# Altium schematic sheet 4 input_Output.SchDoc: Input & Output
size A4
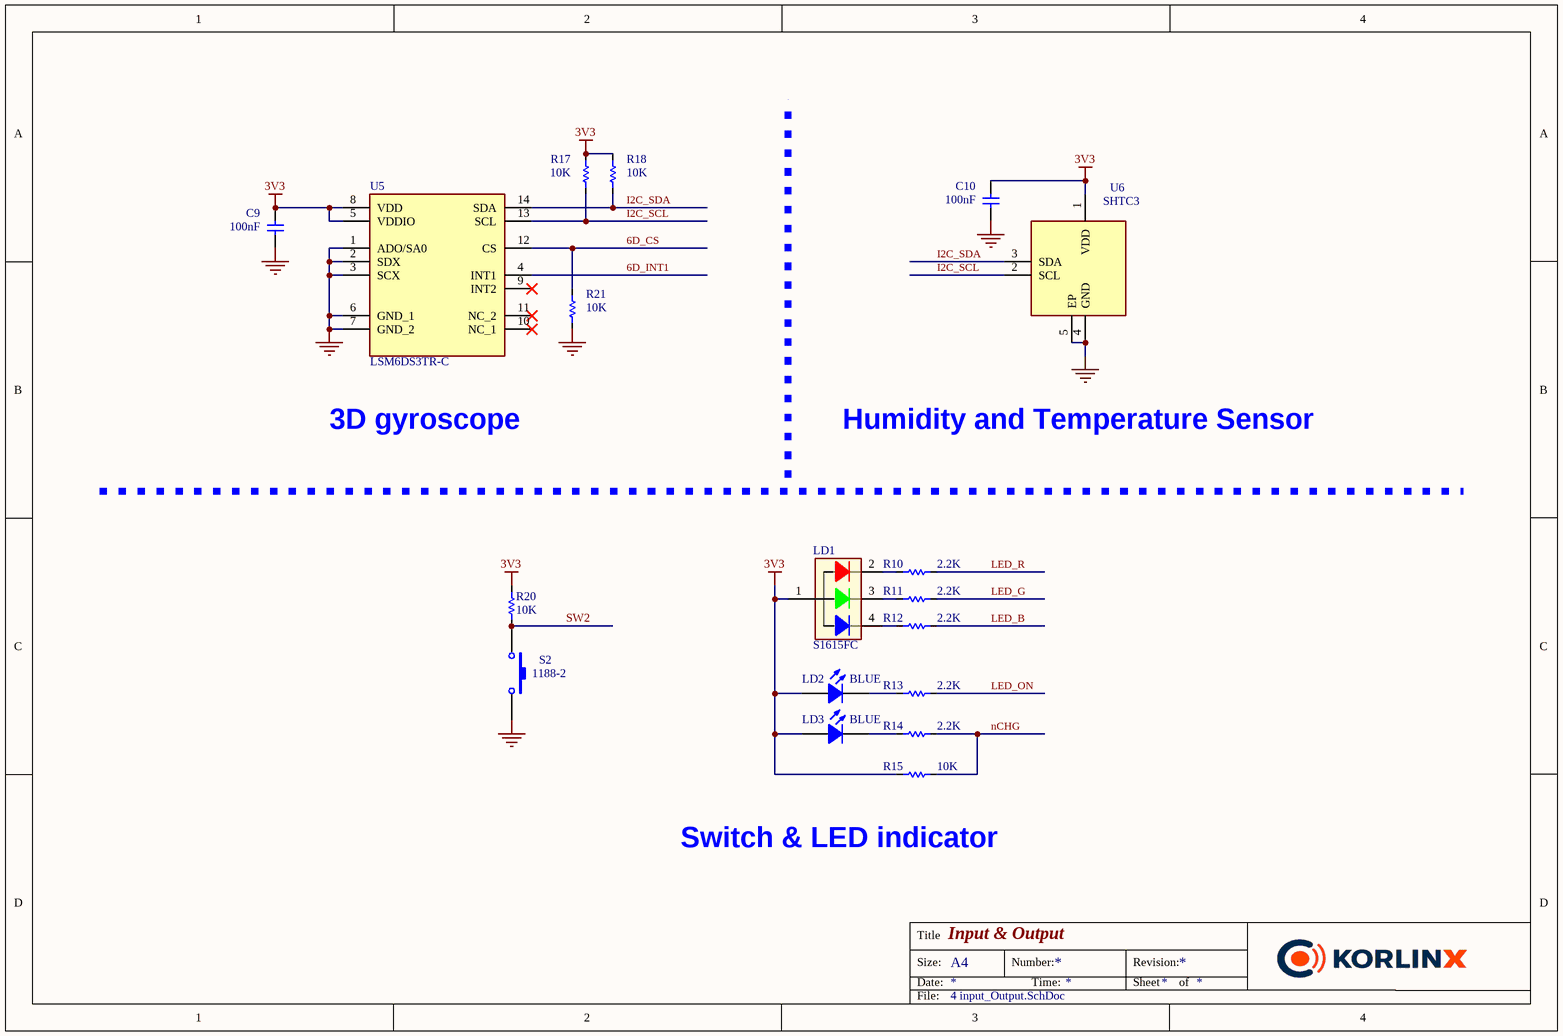
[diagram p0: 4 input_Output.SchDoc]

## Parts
C9  100nF  [CAP 0402/1005]
C10  100nF  [CAP 0402/1005]
LD1  S1615FC  [LED/S1615]
LD2  BLUE  [LED 0402/1005]
LD3  BLUE  [LED 0402/1005]
R10  2.2K  [RES 0402/1005]
R11  2.2K  [RES 0402/1005]
R12  2.2K  [RES 0402/1005]
R13  2.2K  [RES 0402/1005]
R14  2.2K  [RES 0402/1005]
R15  10K  [RES 0402/1005]
R17  10K  [RES 0402/1005]
R18  10K  [RES 0402/1005]
R20  10K  [RES 0402/1005]
R21  10K  [RES 0402/1005]
S2  1188-2  [SW TACT NANOT-AS]
U5  LSM6DS3TR-C  [LGA-14]
U6  SHTC3  [UDFN-4/ SON100P200X200X80-5N]

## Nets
3V3: C9.2 C10.2 LD1.1 LD2.1(A) LD3.1(A) R15.1 R17.1 R18.1 R20.1 U5.5(VDDIO) U5.8(VDD) U6.1(VDD)
GND: C9.1 C10.1 R21.2 S2.2 U5.1(ADO/SA0) U5.2(SDX) U5.3(SCX) U5.6(GND_1) U5.7(GND_2) U6.4(GND) U6.5(EP)
6D_CS: R21.1 U5.12(CS)
6D_INT1: U5.4(INT1)
I2C_SCL: R17.2 U5.13(SCL) U6.2(SCL)
I2C_SDA: R18.2 U5.14(SDA) U6.3(SDA)
LED_B: R12.2
LED_G: R11.2
LED_ON: R13.2
LED_R: R10.2
nCHG: R14.2 R15.2
SW2: R20.2 S2.1
NetLD1_2: LD1.2 R10.1
NetLD1_3: LD1.3 R11.1
NetLD1_4: LD1.4 R12.1
NetLD2_2: LD2.2(K) R13.1
NetLD3_2: LD3.2(K) R14.1

Not connected (* = marked no-connect by the designer): U5 9(INT2)* 10(NC_1)* 11(NC_2)*

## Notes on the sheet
- 3D gyroscope
- Humidity and Temperature Sensor
- (near R15) Switch & LED indicator

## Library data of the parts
C9 C10 = Cap: Capacitor MLCC
LD1 = LED/ S1615FC: LED / RGB; Manufacturer_Part_Number: MSL0601RGBU1; Vendor: ROHM Semiconductor; Built_By: EMA_Matt; SourceLibrary: Rohm_2019-09-23; Type: DEV
LD2 LD3 = LED0: LED
R10-R15 R17 R18 R20 R21 = Res1_1: Resistor
S2 = SW-PB: Switch INSUNG-TECHWIN
U5 = LSM6DS3TR-C: Integrated Circuit; Manufacturer_Name: STMicroelectronics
